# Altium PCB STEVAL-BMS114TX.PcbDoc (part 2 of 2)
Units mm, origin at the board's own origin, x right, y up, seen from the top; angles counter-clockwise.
Board outline 75.8 x 95.1 mm, 4 copper layers (Top Layer, Layer 1, Layer 2, Bottom Layer), stack 1.59 mm thick; 304 components, 148 nets, 694 pads, 400 vias.
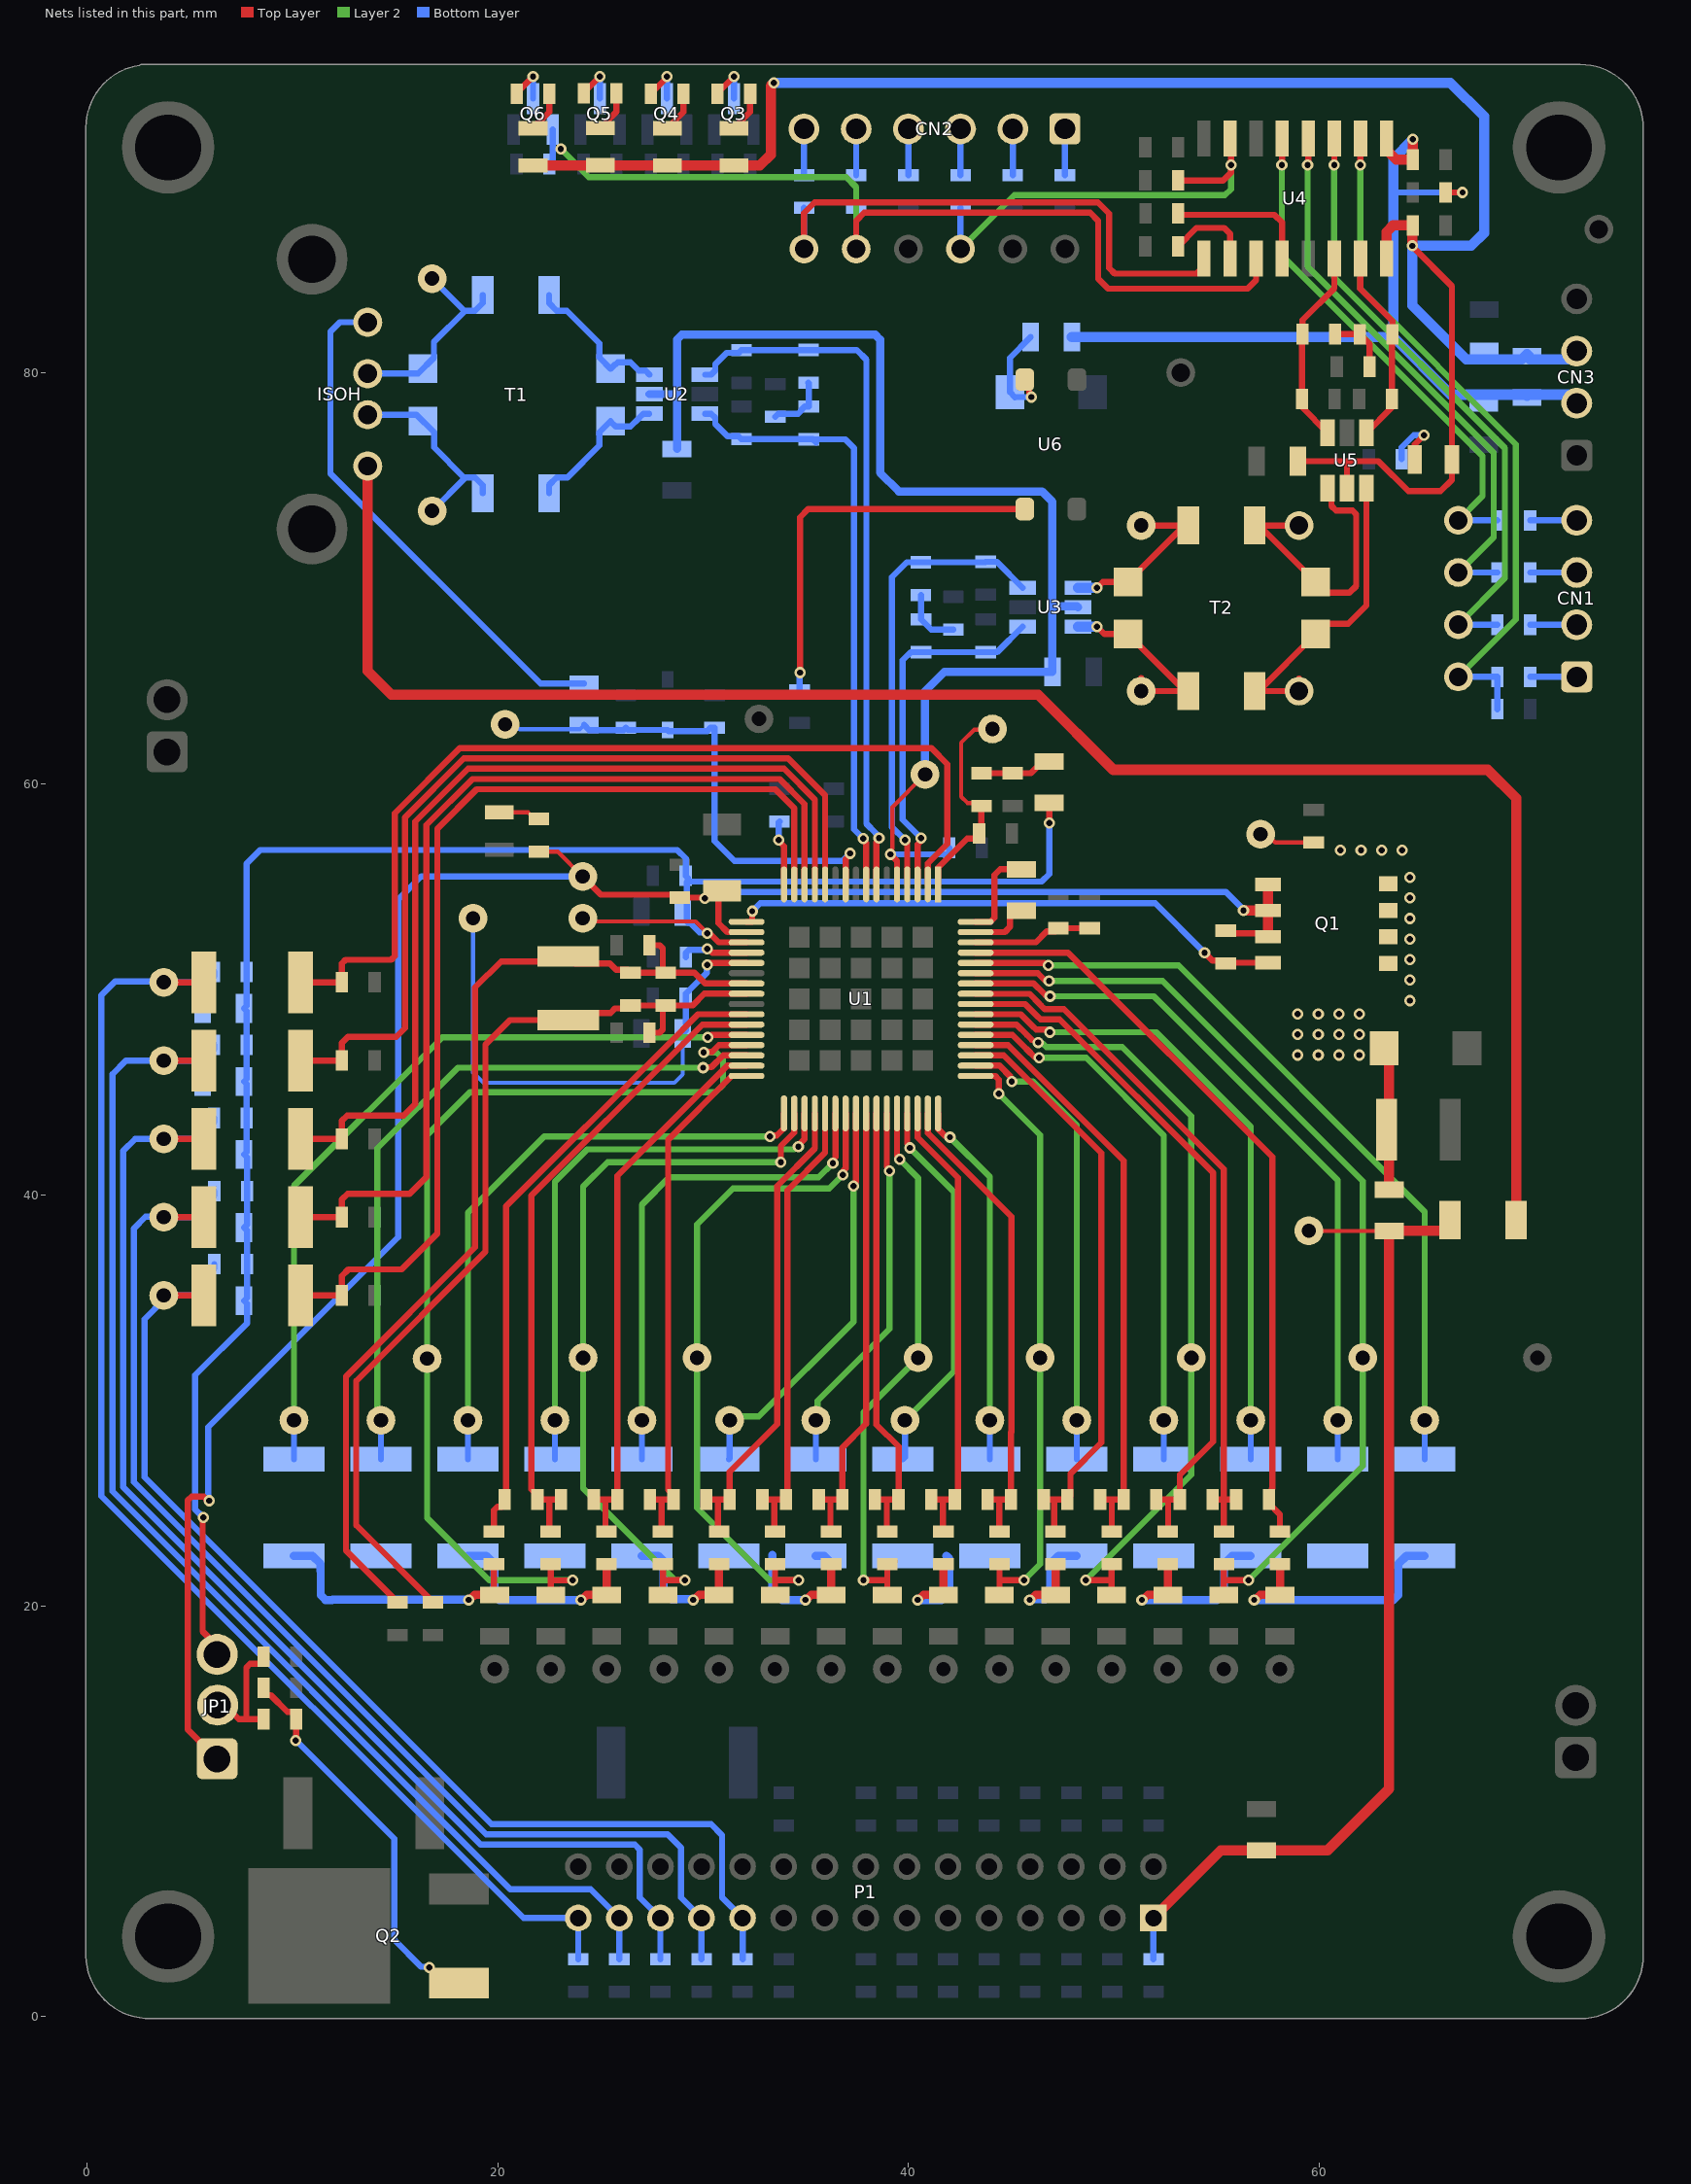
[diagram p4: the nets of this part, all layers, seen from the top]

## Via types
v1: diameter 0.55, hole 0.3, Top Layer to Bottom Layer, tented both sides, 364 vias
v2: diameter 0.55, hole 0.3, Top Layer to Bottom Layer, 36 vias

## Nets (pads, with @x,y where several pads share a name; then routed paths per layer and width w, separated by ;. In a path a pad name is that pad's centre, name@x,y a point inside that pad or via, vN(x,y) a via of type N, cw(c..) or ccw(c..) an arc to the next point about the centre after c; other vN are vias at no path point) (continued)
ISOFreq: R66.2 R80.2 TP10.1 U4.7 | length 22
  Top Layer w0.3: R66.2@53.121,89.372 55.309,89.372 55.695,89.758 v1(55.695,90.129) 55.695,91.367 U4.7@55.652,91.41
  Layer 2 w0.3: TP10.1@42.535,86.036 45.147,88.648 55.397,88.648 55.695,88.946 v1(55.695,90.129)
  Bottom Layer w0.3: TP10.1@42.535,86.036 R80.2@42.535,88.038
ISOLm: C81.2 ISOLm.1 T2.3 U3.4 | length 9
  Top Layer w0.3: v1(49.181,69.552) 49.462,69.833 T2.3@50.677,69.833 C81.2@53.422,72.578 ; ISOLm.1@51.322,72.295 ISOLm.1@51.322,72.578 C81.2@53.422,72.578 ; C81.2@53.618,72.578 C81.2@53.422,72.578
  Bottom Layer w0.5: U3.4@48.255,69.549 49.178,69.549 v1(49.181,69.552)
ISOLp: C27.2 ISOLp.1 T2.4 U3.6 | length 9.3
  Top Layer w0.3: v1(49.181,67.649) 49.537,67.293 T2.4@50.677,67.293 53.455,64.515 ISOLp.1@51.322,64.515 ISOLp.1@51.322,65.16
  Bottom Layer w0.5: U3.6@48.255,67.649 v1(49.181,67.649)
NCS: R73.2 TP7.1 U4.5 | length 25
  Top Layer w0.3: v1(58.171,90.129) 58.192,90.15 U4.5@58.192,91.41
  Layer 2 w0.3: v1(58.171,90.129) 58.171,85.728 67.944,75.955 67.944,74.008 TP7.1@66.764,72.828
  Bottom Layer w0.3: TP7.1@66.764,72.828 R73.2@68.665,72.828
NetB2_1_1: B2_1.1 FB15.2 R56.1 U1.29 | length 50.1
  Top Layer w0.3: R56.1@22.569,22.02 22.585,22.005 22.585,21.267 ; FB15.2@23.064,20.779 22.814,20.529 FB15.2@22.585,20.529 22.585,21.267 ; v1(23.652,21.246) 23.64,21.234 22.617,21.234 22.585,21.267 ; v1(30.03,46.937) 30.052,46.959 30.443,46.959 30.77,47.286 U1.29@32.116,47.286
  Layer 2 w0.3: v1(23.652,21.246) 19.592,21.246 16.568,24.27 16.568,32.07 16.568,42.909 18.647,44.988 30.608,44.988 30.97,45.35 30.97,46.624 30.658,46.937 v1(30.03,46.937)
NetB4_3_1: B4_3.1 FB13.2 R44.1 U1.34 | length 37
  Top Layer w0.3: FB13.2@28.046,20.529 28.046,21.246 ; R44.1@28.246,22.02 R44.1@28.046,22.02 28.046,21.246 ; v1(29.111,21.246) 28.046,21.246 ; v1(33.784,41.586) 33.784,42.367 33.896,42.479 33.896,42.484 34.441,43.029 U1.34@34.441,43.961
  Layer 2 w0.3: v1(29.111,21.246) 28.634,21.246 24.162,25.717 B4_3.1@24.162,32.07 24.162,40.399 25.349,41.586 v1(33.784,41.586)
NetB6_5_1: B6_5.1 FB11.2 R33.1 U1.39 | length 34.2
  Top Layer w0.3: FB11.2@33.507,20.529 33.507,21.275 ; R33.1@33.507,22.02 33.507,21.275 ; R33.1@33.657,22.17 R33.1@33.857,22.17 ; v1(34.653,21.246) 33.535,21.246 33.507,21.275 ; v1(36.802,40.974) 36.85,41.022 36.85,41.195 36.941,41.286 U1.39@36.941,43.961
  Layer 2 w0.3: B6_5.1@29.706,31.883 B6_5.1@29.706,31.824 ; v1(34.653,21.246) 33.235,21.246 29.706,24.775 B6_5.1@29.706,31.824 ; v1(36.802,40.974) 36.802,40.972 36.137,40.307 31.451,40.307 29.706,38.562 B6_5.1@29.706,31.824
NetB8_7_1: B8_7.1 FB9.2 R26.1 U1.44 | length 26.9
  Top Layer w0.3: v1(37.808,21.246) 38.939,21.246 38.968,21.275 ; FB9.2@38.968,20.529 38.968,21.275 ; R26.1@38.968,22.02 38.968,21.275 ; R26.1@39.168,22.02 R26.1@39.318,22.17 ; v1@39.441,41.919 U1.44@39.441,43.961
  Layer 2 w0.3: v1(37.808,21.246) 37.808,29.404 B8_7.1@40.52,32.116 ; v1(39.566,41.726) 40.474,40.818 B8_7.1@40.474,32.07
NetB10_9_1: B10_9.1 FB7.2 R21.1 U1.49 | length 29.4
  Top Layer w0.3: U1.49@43.266,45.786 44.225,45.786 44.401,45.61 44.401,44.931 v1(44.391,44.921) ; FB7.2@44.429,20.529 44.429,21.275 ; R21.1@44.429,22.02 44.429,21.275 ; v1(45.632,21.246) 44.458,21.246 44.429,21.275
  Layer 2 w0.3: v1(44.391,44.921) 46.408,42.904 B10_9.1@46.408,32.07 46.408,22.022 v1(45.632,21.246)
NetB12_11_1: B12_11.1 FB5.2 R14.1 U1.54 | length 39.3
  Top Layer w0.3: U1.54@43.266,48.286 43.982,48.286 45.261,48.286 45.76,47.787 45.836,47.711 46.008,47.538 ; v1(48.632,21.246) 49.767,21.246 ; FB5.2@49.89,20.529 49.89,21.123 49.89,21.246 R14.1@49.89,22.02
  Layer 2 w0.3: v1(46.31,47.413) 46.358,47.366 46.535,47.366 46.706,47.194 50.406,47.194 53.769,43.831 B12_11.1@53.769,32.07 53.769,26.383 v1(48.632,21.246)
NetB14_13_1: B14_13.1 FB3.2 R8.1 U1.59 | length 47.5
  Top Layer w0.3: U1.59@43.266,50.786 46.296,50.786 46.622,50.46 46.799,50.46 v1(46.847,50.412) ; FB3.2@55.351,20.529 55.351,21.123 R8.1@55.351,22.02 ; 55.351,21.246 v1(56.56,21.246)
  Layer 2 w0.3: v1(46.847,50.412) 52.36,50.412 62.113,40.659 62.113,32.413 B14_13.1@62.544,31.982 ; v1(56.56,21.246) 62.113,26.799 B14_13.1@62.113,31.824
NetC3_2: C3.2 C4.2 C5.2 C6.2 D1.2 FB1.2 Q1.5 Q1.6 Q1.7 Q1.8 TP1.1 U1.62 | length 15.6
  Top Layer w0.2: TP1.1@57.137,57.55 57.449,57.55 57.854,57.145 C6.2@59.722,57.145
  Top Layer w0.3: U1.62@43.266,52.286 46.186,52.286 46.728,52.828 47.146,52.828 C4.2@47.296,52.978 C5.2@48.817,52.978
  Top Layer w0.5: D1.2@63.16,47.132 63.399,46.893 FB1.2@63.399,40.258
  other v1: 58.949,46.801 59.949,46.801 60.949,46.801 61.949,46.801 58.949,47.801 59.949,47.801 60.949,47.801 61.949,47.801 58.949,48.801 59.949,48.801 60.949,48.801 61.949,48.801 64.4,49.451 64.4,50.451 64.4,51.451 64.4,52.451 64.4,53.451 64.4,54.451 64.4,55.451 61.031,56.772 62.031,56.772 63.031,56.772 64.031,56.772
NetC9_1: C9.1 C17.2 R8.2 U1.57 | length 34.6
  Top Layer w0.3: U1.57@43.266,49.786 43.991,49.786 45.882,49.786 46.381,49.287 46.457,49.211 46.63,49.038 47.567,49.038 55.351,41.255 55.351,25.173 ; C17.2@54.803,25.373 C17.2@54.803,25.173 55.351,25.173 ; R8.2@55.351,23.614 55.351,25.173 ; C9.1@55.949,25.173 55.351,25.173
NetC9_2: C9.2 R4.2 U1.61 | length 37.1
  Top Layer w0.3: U1.61@43.266,51.786 47.769,51.786 57.708,41.847 57.708,25.711 57.692,25.695 57.692,25.135 57.542,24.985 58.081,24.446 R4.2@58.081,23.614
NetC12_2: C12.2 C13.2 U1.21 VANA.1 | length 25.9
  Top Layer w0.3: v1(30.207,51.195) 30.275,51.195 30.366,51.286 U1.21@32.116,51.286
  Bottom Layer w0.2: VANA.1@18.805,53.461 18.805,45.951 19.306,45.45 28.6,45.45 29.012,45.862 C13.2@29.012,47.863
  Bottom Layer w0.3: C13.2@29.012,47.863 29.155,48.006 C12.2@29.155,49.588 29.155,49.788 29.305,49.938 29.314,49.938 30.176,50.8 30.176,51.164 v1(30.207,51.195)
NetC16_2: C16.2 R36.1 U4.15 U5.1 | length 9.6
  Top Layer w0.3: U4.15@62.002,85.56 62.002,84.086 63.557,82.531 R36.1@63.557,81.88 63.528,81.851 C16.2@63.528,78.738 63.528,78.333 U5.1@62.293,77.098
NetC17_1: C17.1 C20.2 R11.2 U1.56 | length 34.2
  Top Layer w0.3: U1.56@43.266,49.286 43.988,49.286 45.675,49.286 46.174,48.787 46.25,48.711 46.423,48.538 47.36,48.538 54.819,41.079 54.819,27.987 53.21,26.377 C17.1@53.21,25.173 52.637,25.173 ; C20.2@52.064,25.173 52.637,25.173 ; R11.2@52.62,23.614 52.637,23.631 52.637,25.173
NetC18_1: C18.1 U1.64 | length 4.5
  Top Layer w0.3: U1.64@43.266,53.286 43.991,53.286 44.19,53.485 44.19,55.567 44.468,55.845 C18.1@45.498,55.845
NetC18_2: C18.2 U1.63 | length 3
  Top Layer w0.3: U1.63@43.266,52.786 44.689,52.786 44.948,53.045 44.948,53.582 45.198,53.832 C18.2@45.498,53.832
NetC20_1: C20.1 C23.2 R14.2 U1.52 | length 28.7
  Top Layer w0.3: U1.52@43.266,47.286 44.847,47.286 50.471,41.662 C20.1@50.471,25.173 49.898,25.173 ; C23.2@49.325,25.173 49.898,25.173 ; R14.2@49.89,23.614 49.898,23.622 49.898,25.173
NetC22_2: C22.2 R15.2 U1.7 U2.1 | length 34.6
  Top Layer w0.3: U1.7@38.441,55.111 38.441,57.163 38.566,57.288 v1(38.566,57.356)
  Bottom Layer w0.3: U2.1@30.096,79.919 30.396,79.919 30.596,80.119 30.596,80.419 31.158,80.981 31.738,80.981 C22.2@31.866,81.109 35.122,81.109 R15.2@35.131,81.118 37.48,81.118 37.951,80.648 37.951,58.063 38.416,57.598 38.416,57.574 38.566,57.423 v1(38.566,57.356)
NetC23_1: C23.1 C30.2 R17.2 U1.51 | length 28.2
  Top Layer w0.3: U1.51@43.266,46.786 44.639,46.786 49.388,42.037 49.388,27.938 47.882,26.432 47.882,25.323 C23.1@47.732,25.173 ; C30.2@46.587,25.173 47.084,25.173 ; R17.2@47.159,23.614 47.084,23.688 47.084,25.173 ; C23.1@47.582,25.173 47.084,25.173
NetC24_1: C24.1 R15.1 R18.2 | length 3
  Bottom Layer w0.3: C24.1@33.517,77.865 33.667,78.015 34.621,78.015 34.797,78.191 34.797,78.213 34.947,78.363 R18.2@35.147,78.363 35.147,79.509 R15.1@35.131,79.525
NetC26_1: C26.1 R18.1 U1.8 U2.3 | length 30
  Top Layer w0.3: v1(37.791,57.339) 37.791,57.271 37.941,57.121 U1.8@37.941,55.111
  Bottom Layer w0.3: U2.3@30.096,78.019 30.396,78.019 30.596,77.819 30.596,77.519 31.185,76.93 31.716,76.93 C26.1@31.866,76.78 35.338,76.78 R18.1@35.347,76.77 ; R18.1@35.147,76.77 R18.1@35.347,76.77 ; R18.1@35.497,76.62 R18.1@35.347,76.77 ; v1(37.791,57.339) 37.344,57.786 37.344,76.347 36.921,76.77 35.497,76.77 R18.1@35.347,76.77
NetC27_1: C27.1 T2.1 TP2.1 U5.6 | length 15.3
  Top Layer w0.3: TP2.1@59.007,65.13 TP2.1@59.007,64.515 57.043,64.515 T2.1@59.821,67.293 60.329,67.801 61.404,67.801 62.293,68.69 U5.6@62.293,74.398
NetC28_1: C28.1 T1.1 U2.6 | length 7.3
  Bottom Layer w0.3: C28.1@22.504,83.798 22.504,83.397 22.878,83.023 23.376,83.023 24.953,81.447 24.953,80.75 T1.1@25.501,80.202 T1.1@25.714,80.415 ; T1.1@25.78,80.447 25.855,80.522 26.474,80.522 26.877,80.119 27.196,80.119 U2.6@27.396,79.919
NetC28_2: C28.2 ISOH.3 ISOHp.1 T1.4 | length 10.1
  Bottom Layer w0.3: ISOH.3@13.675,79.969 16.124,79.969 16.902,80.747 16.902,81.506 18.418,83.021 ; ISOHp.1@16.811,84.593 18.383,83.021 18.418,83.021 ; C28.2@19.278,83.798 19.278,83.397 18.904,83.023 18.73,83.023 18.728,83.021 18.418,83.021
NetC30_1: C30.1 C32.2 R21.2 U1.47 | length 23.2
  Top Layer w0.3: U1.47@40.941,43.961 40.941,43.001 45.007,38.935 45.007,28.462 44.993,28.448 C30.1@44.993,25.173 44.42,25.173 ; C32.2@43.848,25.173 44.42,25.173 ; R21.2@44.429,23.614 44.42,23.622 44.42,25.173
NetC32_1: C32.1 C35.2 R23.2 U1.46 | length 22.4
  Top Layer w0.3: U1.46@40.441,43.961 40.441,43.236 40.441,42.794 42.404,40.831 42.404,25.323 C32.1@42.254,25.173 41.682,25.173 ; C35.2@41.109,25.173 41.682,25.173 ; R23.2@41.698,23.614 41.682,23.63 41.682,25.173
NetC34_2: C34.2 R25.2 U1.3 U3.1 | length 17.9
  Top Layer w0.3: U1.3@40.441,55.111 40.441,57.056 40.559,57.174 40.559,57.323 v1(40.607,57.371)
  Bottom Layer w0.3: v1(40.607,57.371) 39.72,58.258 39.72,66.021 40.107,66.408 R25.2@40.612,66.408 C34.2@43.754,66.408 44.314,66.408 U3.1@45.555,67.649
NetC35_1: C35.1 C41.2 R26.2 U1.42 | length 21.9
  Top Layer w0.3: C41.2@38.37,25.173 38.943,25.173 ; U1.42@38.441,43.961 38.441,43.236 38.441,28.822 39.515,27.747 C35.1@39.515,25.173 38.943,25.173 ; R26.2@38.968,23.614 38.943,23.639 38.943,25.173
NetC36_1: C36.1 R25.1 R27.2 | length 3
  Bottom Layer w0.3: R27.2@40.604,69.196 40.604,68.01 R25.1@40.612,68.002 41.103,67.511 C36.1@42.183,67.511
NetC38_1: C38.1 T1.2 U2.4 | length 7.3
  Bottom Layer w0.3: C38.1@22.504,74.146 22.504,74.545 22.878,74.919 23.405,74.919 24.955,76.469 24.955,77.116 T1.2@25.501,77.662 ; T1.2@25.501,77.637 25.747,77.391 26.474,77.391 26.896,77.813 26.896,77.819 27.096,78.019 U2.4@27.374,78.019
NetC38_2: C38.2 ISOH.2 ISOHm.1 T1.3 | length 10.2
  Bottom Layer w0.3: ISOH.2@13.675,77.969 16.05,77.969 16.905,77.114 16.905,76.373 18.362,74.915 18.437,74.915 ; ISOHm.1@16.811,73.289 18.437,74.915 ; C38.2@19.278,74.146 19.278,74.541 18.904,74.915 18.437,74.915
NetC39_1: C39.1 R27.1 U1.4 U3.3 | length 22.5
  Top Layer w0.3: v1(39.824,57.27) 39.85,57.295 39.941,57.204 U1.4@39.941,55.111
  Bottom Layer w0.3: v1(39.824,57.27) 39.2,57.894 39.2,70.067 39.923,70.789 R27.1@40.604,70.789 43.736,70.789 C39.1@43.754,70.808 44.296,70.808 U3.3@45.555,69.549
NetC41_1: C41.1 C43.2 R29.2 U1.41 | length 22
  Top Layer w0.3: C43.2@35.631,25.173 36.204,25.173 ; R29.2@36.237,23.614 36.204,23.647 36.204,25.173 ; U1.41@37.941,43.961 37.941,28.853 36.777,27.689 C41.1@36.777,25.173 36.204,25.173
NetC43_1: C43.1 C46.2 R33.2 U1.37 | length 22.3
  Top Layer w0.3: C46.2@32.892,25.173 33.465,25.173 ; R33.2@33.507,23.614 33.465,23.655 33.465,25.173 ; U1.37@35.941,43.961 35.941,43.236 35.941,42.054 34.106,40.219 34.106,25.242 C43.1@34.038,25.173 33.465,25.173
NetC44_2: C44.2 D3.2 GPIO1.1 R30.1 R32.2 U1.10 | length 24.9
  Top Layer w0.3: U1.10@36.941,55.111 36.941,56.338 37.153,56.55 v1(37.153,56.618)
  Bottom Layer w0.2: GPIO1.1@20.364,62.901 20.594,62.672 21.066,62.672 21.081,62.657 23.999,62.657 R30.1@24.21,62.868
  Bottom Layer w0.3: R30.1@24.21,62.868 24.456,62.622 26.139,62.622 R32.2@26.242,62.725 26.343,62.624 D3.2@28.27,62.624 28.321,62.572 30.207,62.572 30.36,62.725 C44.2@30.56,62.725 30.56,57.227 31.533,56.254 36.789,56.254 v1(37.153,56.618)
NetC46_1: C46.1 C49.2 R40.2 U1.36 | length 23.2
  Top Layer w0.3: C49.2@30.153,25.173 30.726,25.173 ; R40.2@30.776,23.614 30.726,23.664 30.726,25.173 ; U1.36@35.441,43.961 35.441,42.261 33.606,40.426 33.606,28.832 31.299,26.525 C46.1@31.299,25.173 30.726,25.173
NetC49_1: C49.1 C51.2 R44.2 U1.32 | length 25.5
  Top Layer w0.3: C51.2@27.416,25.173 27.988,25.173 ; R44.2@28.046,23.614 27.988,23.671 27.988,25.173 ; U1.32@32.116,45.786 31.391,45.786 31.391,45.771 28.297,42.677 28.297,25.636 28.56,25.373 C49.1@28.56,25.173 27.988,25.173
NetC51_1: C51.1 C58.2 R51.2 U1.31 | length 27
  Top Layer w0.3: C58.2@24.678,25.173 25.25,25.173 ; R51.2@25.3,23.614 25.25,23.664 25.25,25.173 ; U1.31@32.116,46.286 31.184,46.286 28.06,43.162 25.822,40.924 C51.1@25.822,25.173 25.25,25.173
NetC58_1: C58.1 C60.2 R56.2 U1.27 | length 31.4
  Top Layer w0.3: C60.2@21.94,25.173 22.512,25.173 ; C60.2@21.94,25.373 21.644,25.669 21.644,39.964 29.037,47.357 29.966,48.286 U1.27@32.116,48.286 ; R56.2@22.569,23.614 22.512,23.671 22.512,25.173 ; C58.1@23.084,25.173 22.512,25.173
NetC60_1: C60.1 R60.2 U1.26 | length 31.8
  Top Layer w0.3: R60.2@19.82,23.614 19.82,24.647 19.996,24.823 20.196,24.823 20.346,24.973 C60.1@20.346,25.173 20.417,25.244 20.417,39.444 28.238,47.265 29.759,48.786 31.391,48.786 U1.26@32.116,48.786
NetC61_2: C61.2 R53.1 U1.2 | length 47.4
  Top Layer w0.3: R53.1@10.403,50.343 C61.2@12.421,50.343 12.421,51.264 12.597,51.44 14.817,51.44 14.992,51.616 14.992,58.577 18.153,61.738 41.119,61.738 41.892,60.966 41.892,57.082 40.941,56.131 U1.2@40.941,55.111
NetC62_2: C62.2 R54.1 U1.12 | length 43.2
  Top Layer w0.3: R54.1@10.403,46.533 C62.2@12.421,46.533 12.421,47.393 12.711,47.683 15.063,47.683 15.492,48.112 15.492,58.37 18.36,61.238 34.143,61.238 35.941,59.44 U1.12@35.941,55.111
NetC63_2: C63.2 R55.1 U1.13 | length 45.8
  Top Layer w0.3: R55.1@10.403,42.723 C63.2@12.421,42.723 12.421,43.611 12.672,43.862 15.429,43.862 15.992,44.426 15.992,58.163 18.567,60.738 33.936,60.738 35.441,59.233 U1.13@35.441,55.111
NetC64_2: C64.2 R57.1 U1.14 | length 48.3
  Top Layer w0.3: R57.1@10.403,38.913 C64.2@12.421,38.913 12.421,39.777 12.698,40.054 15.719,40.054 16.53,40.865 16.53,57.994 18.774,60.238 33.729,60.238 34.941,59.026 U1.14@34.941,55.111
NetC65_2: C65.2 R58.1 U1.15 | length 50.4
  Top Layer w0.3: R58.1@10.403,35.103 C65.2@12.421,35.103 12.421,36.059 12.736,36.374 15.329,36.374 17.062,38.107 17.062,57.819 18.981,59.738 33.522,59.738 34.441,58.819 U1.15@34.441,55.111
NetC72_1: C72.1 C73.1 C74.1 R7.2 R10.1 U1.24 | length 47
  Top Layer w0.3: R7.2@16.856,20.172 13.118,23.91 13.118,30.948 19.404,37.234 19.404,47.31 20.598,48.504 C72.1@23.431,48.504 23.781,48.854 25.501,48.854 25.717,49.07 26.318,49.07 C73.1@26.465,49.217 C74.1@28.19,49.217 ; R10.1@27.387,47.888 27.887,47.888 28.037,48.038 28.037,48.412 28.038,48.413 28.038,49.067 28.188,49.217 C74.1@28.19,49.217 ; U1.24@32.116,49.786 30.062,49.786 29.493,49.217 C74.1@28.19,49.217
NetC72_2: C72.2 C73.2 C74.2 R3.2 R13.1 U1.23 | length 49.7
  Top Layer w0.3: R3.2@15.131,20.172 12.618,22.685 12.618,31.155 18.904,37.441 18.904,50.093 20.174,51.363 23.191,51.363 C72.2@23.431,51.603 23.773,51.26 25.464,51.26 25.771,50.953 26.322,50.953 C73.2@26.465,50.81 C74.2@27.93,50.81 ; R13.1@27.387,52.146 27.887,52.146 28.037,51.996 28.037,51.622 28.038,51.621 28.038,50.877 28.105,50.81 C74.2@28.19,50.81 29.576,50.81 30.1,50.286 U1.23@32.116,50.286
NetC79_2: C79.2 R36.2 R42.1 | length 3
  Top Layer w0.3: R42.1@60.77,81.889 61.955,81.889 R36.2@61.964,81.88 62.436,81.408 C79.2@62.436,80.309
NetC81_1: C81.1 T2.2 TP3.1 U5.4 | length 14.5
  Top Layer w0.3: C81.1@56.844,72.578 C81.1@57.076,72.578 ; TP3.1@59.007,72.31 TP3.1@59.007,72.578 C81.1@57.076,72.578 ; U5.4@60.393,74.398 60.585,74.205 60.585,73.529 60.812,73.302 61.609,73.302 61.793,73.118 61.793,69.629 61.464,69.3 60.354,69.3 T2.2@59.821,69.833 C81.1@57.076,72.578
NetC82_2: C82.2 R42.2 U4.14 U5.3 | length 9.6
  Top Layer w0.3: U5.3@60.393,77.098 59.154,78.336 C82.2@59.154,78.738 59.154,81.867 R42.2@59.176,81.889 59.176,82.57 60.732,84.126 U4.14@60.732,85.56
NetCGS_2: CGS.2 Q2.1 RG.1 | length 17.5
  Top Layer w0.3: CGS.2@8.603,15.999 8.603,15.799 8.753,15.649 8.953,15.649 9.774,14.828 10.046,14.828 10.196,14.678 10.196,13.467 v1(10.171,13.442)
  Bottom Layer w0.3: v1(10.171,13.442) 10.189,13.442 14.966,8.665 14.966,3.741 16.279,2.428 16.631,2.428 v1(16.667,2.392)
NetCN1_1: CN1.1 R69.1 | length 2.3
  Bottom Layer w0.3: R69.1@70.259,65.208 CN1.1@72.528,65.208
NetCN1_2: CN1.2 R70.1 | length 2.3
  Bottom Layer w0.3: R70.1@70.259,67.748 CN1.2@72.528,67.748
NetCN1_3: CN1.3 R72.1 | length 2.3
  Bottom Layer w0.3: R72.1@70.259,70.288 CN1.3@72.528,70.288
NetCN1_4: CN1.4 R73.1 | length 2.3
  Bottom Layer w0.3: R73.1@70.259,72.828 CN1.4@72.528,72.828
NetCN2_1: CN2.1 R75.1 | length 2.3
  Bottom Layer w0.3: R75.1@47.615,89.631 CN2.1@47.615,91.881
NetCN2_2: CN2.2 R76.1 | length 2.3
  Bottom Layer w0.3: R76.1@45.075,89.631 CN2.2@45.075,91.881
NetCN2_3: CN2.3 R80.1 | length 2.3
  Bottom Layer w0.3: R80.1@42.535,89.631 CN2.3@42.535,91.881
NetCN2_4: CN2.4 R82.1 | length 2.3
  Bottom Layer w0.3: R82.1@39.995,89.631 CN2.4@39.995,91.881
NetCN2_5: CN2.5 R83.1 | length 2.3
  Bottom Layer w0.3: R83.1@37.455,89.631 CN2.5@37.455,91.881
NetCN2_6: CN2.6 R84.1 | length 2.3
  Bottom Layer w0.3: R84.1@34.915,89.631 CN2.6@34.915,91.881
NetD2_1: D2.1 R5.1 | length 2
  Top Layer w0.2: D2.1@20.088,58.612 21.486,58.612 21.603,58.495 21.803,58.294 R5.1@22.003,58.294
NetD4_2: D4.2 R67.2 U6.4 | length 5.2
  Top Layer w0.3: U6.4@45.66,79.677 45.877,79.46 45.877,78.938 v1(45.987,78.827)
  Bottom Layer w0.3: R67.2@45.943,81.746 44.935,80.737 D4.2@44.935,79.068 45.184,78.819 45.192,78.827 v1(45.987,78.827)
NetD5_2: D5.2 R74.2 | length 2
  Top Layer w0.3: D5.2@31.504,91.908 32.294,92.698 R74.2@32.294,93.595
NetD6_2: D6.2 R77.2 | length 2
  Top Layer w0.3: D6.2@28.257,91.908 29.05,92.701 R77.2@29.05,93.595
NetD7_2: D7.2 R78.2 | length 2
  Top Layer w0.3: D7.2@24.994,91.918 25.787,92.711 R78.2@25.787,93.605
NetD8_2: D8.2 R79.2 | length 2
  Top Layer w0.3: D8.2@21.726,91.908 22.519,92.701 R79.2@22.519,93.595
NetD9_2: D9.2 R89.2 | length 3.3
  Top Layer w0.3: D9.2@64.64,75.787 64.64,76.524 v1(65.086,76.97)
  Bottom Layer w0.3: R89.2@64.001,75.807 64.001,76.383 64.588,76.97 v1(65.086,76.97)
NetFB2_2: FB2.2 R4.1 R6.1 | length 12.9
  Top Layer w0.4: v1(56.824,20.284) 56.865,20.284 57.109,20.529 FB2.2@58.081,20.529 R4.1@58.081,22.02
  Bottom Layer w0.4: v1(56.824,20.284) 63.604,20.284 63.838,20.518 63.838,22.029 64.238,22.429 R6.1@65.126,22.429
NetFB4_2: FB4.2 R9.1 R11.1 R12.1 | length 9.9
  Top Layer w0.4: v1(51.362,20.284) 51.403,20.284 51.647,20.529 FB4.2@52.62,20.529 R11.1@52.62,22.02
  Bottom Layer w0.4: v1(51.362,20.284) 55.01,20.284 55.358,20.632 55.358,22.029 55.758,22.429 R12.1@56.658,22.429
NetFB6_2: FB6.2 R16.1 R17.1 R19.1 | length 6.9
  Top Layer w0.4: v1(45.9,20.284) 45.941,20.284 46.185,20.529 FB6.2@47.159,20.529 R17.1@47.159,22.02
  Bottom Layer w0.4: v1(45.9,20.284) 45.929,20.313 46.665,20.313 46.899,20.547 46.899,22.029 47.299,22.429 R19.1@48.191,22.429
NetFB8_2: FB8.2 R22.1 R23.1 R24.1 | length 6.4
  Top Layer w0.4: v1(40.438,20.284) 40.479,20.284 40.723,20.529 FB8.2@41.698,20.529 R23.1@41.698,22.02
  Bottom Layer w0.4: v1(40.438,20.284) 41.597,20.284 41.983,20.67 41.983,22.286 41.84,22.429
NetFB10_2: FB10.2 R28.1 R29.1 R31.1 | length 7.3
  Top Layer w0.4: v1(34.976,20.284) 35.017,20.284 35.261,20.529 FB10.2@36.237,20.529 R29.1@36.237,22.02
  Bottom Layer w0.4: 33.368,22.473 33.368,20.773 33.857,20.284 v1(34.976,20.284) ; R28.1@35.489,22.429 35.896,22.429 R28.1@36.296,22.029
NetFB12_2: FB12.2 R38.1 R40.1 R41.1 | length 7.1
  Top Layer w0.4: v1(29.514,20.284) 29.555,20.284 29.799,20.529 FB12.2@30.776,20.529 R40.1@30.776,22.02
  Bottom Layer w0.4: R38.1@27.021,22.429 27.825,22.429 28.081,22.174 28.081,20.691 28.459,20.313 29.485,20.313 v1(29.514,20.284)
NetFB14_2: FB14.2 R50.1 R51.1 R52.1 | length 10.1
  Top Layer w0.4: v1(24.052,20.284) 24.093,20.284 24.337,20.529 FB14.2@25.315,20.529 25.315,22.005 R51.1@25.3,22.02
  Bottom Layer w0.4: R50.1@18.554,22.429 19.442,22.429 19.842,22.029 19.842,20.518 20.076,20.284 v1(24.052,20.284)
NetFB16_2: FB16.2 R59.1 R60.1 | length 13.2
  Top Layer w0.3: R60.1@19.82,22.02 19.82,20.563 FB16.2@19.854,20.529
  Top Layer w0.4: v1(18.59,20.284) 18.631,20.284 18.875,20.529 FB16.2@19.854,20.529
  Bottom Layer w0.4: R59.1@10.086,22.429 10.986,22.429 11.386,22.029 11.386,21.695 11.388,21.693 11.388,20.519 11.622,20.285 11.954,20.285 11.968,20.299 18.575,20.299 v1(18.59,20.284)
NetISOH_1: ISOH.1 R1.1 | length 89
  Top Layer w0.5: ISOH.1@13.675,75.469 13.675,65.504 14.836,64.343 46.307,64.343 49.965,60.685 68.194,60.685 69.582,59.297 R1.1@69.582,38.772
NetISOH_4: ISOH.4 R30.2 | length 25.5
  Bottom Layer w0.3: ISOH.4@13.675,82.469 12.316,82.469 11.861,82.013 11.861,75.106 22.086,64.881 R30.2@24.21,64.881
NetJP1_2: JP1.2 RG.2 RPD.2 | length 6.2
  Top Layer w0.3: JP1.2@6.373,15.165 6.712,15.165 7.399,14.478 7.77,14.478 ; RG.2@8.603,14.478 7.77,14.478 ; RPD.2@8.603,17.52 8.603,17.32 8.453,17.17 7.946,17.17 7.77,16.994 7.77,14.478
NetQ1_4: Q1.4 RMREG.1 U1.17 | length 27.3
  Top Layer w0.3: U1.17@32.116,53.286 32.395,53.286 v1(32.395,53.804) ; v1(54.415,51.786) 54.791,51.41 55.292,51.41 RMREG.1@55.442,51.26 55.477,51.296 Q1.4@57.493,51.296
  Bottom Layer w0.3: v1(32.395,53.804) 32.782,54.19 52.011,54.19 v1(54.415,51.786)
NetQ3_3: Q3.3 R74.1 | length 2.2
  Top Layer w0.3: R74.1@30.7,93.595 30.7,93.629 v1(31.504,94.433)
  Bottom Layer w0.3: Q3.3@31.501,93.356 31.501,94.43 v1(31.504,94.433)
NetQ4_3: Q4.3 R77.1 | length 2.2
  Top Layer w0.3: R77.1@27.457,93.595 28.237,94.376 v1(28.237,94.433)
  Bottom Layer w0.3: Q4.3@28.237,93.356 v1(28.237,94.433)
NetQ5_3: Q5.3 R78.1 | length 2.2
  Top Layer w0.3: R78.1@24.193,93.605 24.193,93.643 v1(24.984,94.433)
  Bottom Layer w0.3: Q5.3@24.984,93.356 v1(24.984,94.433)
NetQ6_3: Q6.3 R79.1 | length 2.2
  Top Layer w0.3: R79.1@20.926,93.595 20.926,93.633 v1(21.726,94.433)
  Bottom Layer w0.3: Q6.3@21.726,93.356 v1(21.726,94.433)
NetR6_2: R6.2 S14.1 U1.60 | length 38.9
  Top Layer w0.3: U1.60@43.266,51.286 46.613,51.286 46.738,51.161 v1(46.805,51.161)
  Layer 2 w0.3: v1(46.805,51.161) 53.14,51.161 65.126,39.175 S14.1@65.126,29.028
  Bottom Layer w0.3: R6.2@65.126,27.129 S14.1@65.126,29.028
NetR9_2: R9.2 S13.1 U1.58 | length 35.2
  Top Layer w0.3: U1.58@43.266,50.286 43.991,50.286 46.089,50.286 46.588,49.787 46.664,49.711 46.841,49.711 v1(46.889,49.663)
  Layer 2 w0.3: v1(46.889,49.663) 51.94,49.663 60.892,40.711 S13.1@60.892,29.028
  Bottom Layer w0.3: R9.2@60.892,27.129 S13.1@60.892,29.028
NetR12_2: R12.2 S12.1 U1.55 | length 31.6
  Top Layer w0.3: U1.55@43.266,48.786 43.985,48.786 45.468,48.786 45.967,48.287 46.043,48.211 46.216,48.038 v1@46.685,48.038
  Layer 2 w0.3: v1(46.878,47.913) 52.062,47.913 56.658,43.317 S12.1@56.658,29.028
  Bottom Layer w0.3: R12.2@56.658,27.129 S12.1@56.658,29.028
NetR16_2: R16.2 S11.1 U1.53 | length 27.2
  Top Layer w0.3: U1.53@43.266,47.786 43.979,47.786 45.054,47.786 45.552,47.287 45.628,47.211 45.801,47.038 46.127,46.712 46.304,46.712 v1(46.352,46.665)
  Layer 2 w0.3: v1(46.352,46.665) 48.646,46.665 52.424,42.887 S11.1@52.424,29.028
  Bottom Layer w0.3: R16.2@52.424,27.129 S11.1@52.424,29.028 S11.1@52.635,29.238
NetR19_2: R19.2 S10.1 U1.50 | length 22.5
  Top Layer w0.3: U1.50@43.266,46.286 43.991,46.286 44.432,46.286 44.978,45.74 44.978,45.563 v1(45.026,45.516)
  Layer 2 w0.3: v1(45.026,45.516) 46.063,45.516 48.191,43.388 S10.1@48.191,29.028
  Bottom Layer w0.3: R19.2@48.191,27.129 S10.1@48.191,29.028
NetR20_1: R20.1 U1.20 | length 3.3
  Top Layer w0.3: v1(30.207,51.964) 30.275,51.964 30.453,51.786 U1.20@32.116,51.786
  Bottom Layer w0.3: R20.1@29.163,51.567 29.163,51.767 29.313,51.917 30.16,51.917 v1(30.207,51.964)
NetR22_2: R22.2 S9.1 U1.48 | length 18
  Top Layer w0.3: U1.48@41.441,43.961 41.441,43.208 41.796,42.853 41.973,42.853 v1(42.02,42.805)
  Layer 2 w0.3: v1(42.02,42.805) 43.957,40.869 S9.1@43.957,29.028
  Bottom Layer w0.3: R22.2@43.957,27.129 S9.1@43.957,29.028
NetR24_2: R24.2 S8.1 U1.45 | length 18.8
  Top Layer w0.3: v1@39.941,42.478 U1.45@39.941,43.961
  Layer 2 w0.3: S8.1@39.823,29.028 42.219,31.424 42.219,40.132 v1(40.066,42.285)
  Bottom Layer w0.3: R24.2@39.723,27.129 39.823,27.229 S8.1@39.823,29.028 S8.1@40.021,29.226
NetR28_2: R28.2 S7.1 U1.43 | length 18.7
  Top Layer w0.3: U1.43@38.941,43.961 38.941,41.467 38.941,41.36 39.066,41.235 v1(39.066,41.167)
  Layer 2 w0.3: S7.1@35.489,29.028 35.566,29.105 35.566,29.977 39.066,33.477 v1(39.066,41.167)
  Bottom Layer w0.3: R28.2@35.489,27.129 S7.1@35.489,29.028 S7.1@35.7,29.238
NetR31_2: R31.2 S6.1 U1.40 | length 20.4
  Top Layer w0.3: v1(37.316,40.428) 37.316,40.495 37.441,40.62 U1.40@37.441,43.961
  Layer 2 w0.3: S6.1@31.299,29.028 31.488,29.217 32.718,29.217 37.316,33.815 v1(37.316,40.428)
  Bottom Layer w0.3: R31.2@31.255,27.129 31.299,27.173 S6.1@31.299,29.028 S6.1@31.509,29.238
NetR34_1: R34.1 R35.2 R37.2 | length 3.5
  Top Layer w0.3: R37.2@43.549,60.518 R35.2@45.07,60.518 45.96,60.518 46.544,61.103 R34.1@46.844,61.103
NetR38_2: R38.2 S5.1 U1.38 | length 24.6
  Top Layer w0.3: 36.441,41.847 U1.38@36.441,43.961
  Layer 2 w0.3: S5.1@27.021,29.028 27.021,39.517 28.35,40.846 35.617,40.846 v1(36.316,41.545)
  Bottom Layer w0.3: R38.2@27.021,27.129 S5.1@27.021,29.028
NetR41_2: R41.2 S4.1 U1.35 | length 27.8
  Top Layer w0.3: v1(34.637,42.341) 34.637,42.409 34.941,42.713 U1.35@34.941,43.961
  Layer 2 w0.3: S4.1@22.788,29.028 22.788,40.643 24.356,42.211 34.439,42.211 34.57,42.341 v1(34.637,42.341)
  Bottom Layer w0.3: R41.2@22.788,27.129 S4.1@22.788,29.028
NetR43_1: R43.1 U1.16 | length 3.2
  Top Layer w0.3: v1(33.679,57.264) 33.679,57.225 33.941,56.963 U1.16@33.941,55.111
  Bottom Layer w0.3: v1(33.679,57.264) 33.679,58.13 R43.1@33.721,58.172
NetR50_2: R50.2 S3.1 U1.33 | length 29.8
  Top Layer w0.3: v1(33.261,42.836) 33.309,42.884 33.589,42.884 33.941,43.236 U1.33@33.941,43.961
  Layer 2 w0.3: S3.1@18.554,29.028 18.554,39.124 22.266,42.836 v1(33.261,42.836)
  Bottom Layer w0.3: R50.2@18.554,27.129 S3.1@18.554,29.028
NetR52_2: R52.2 S2.1 U1.30 | length 35.1
  Top Layer w0.3: v1(30.003,46.187) 30.029,46.213 30.403,46.213 30.977,46.786 U1.30@32.116,46.786
  Layer 2 w0.3: S2.1@14.32,29.028 14.143,29.204 14.143,42.266 18.064,46.187 v1(30.003,46.187)
  Bottom Layer w0.3: R52.2@14.32,27.129 S2.1@14.32,29.028 S2.1@14.32,29.051
NetR59_2: R59.2 S1.1 U1.28 | length 38.4
  Top Layer w0.3: v1(30.225,47.661) 30.293,47.661 30.418,47.786 U1.28@32.116,47.786
  Layer 2 w0.3: S1.1@10.086,29.028 10.086,40.442 17.305,47.661 v1(30.225,47.661)
  Bottom Layer w0.3: R59.2@10.086,27.129 S1.1@10.086,29.028
NetR63_1: R63.1 U4.12 | length 7
  Top Layer w0.3: R63.1@53.128,87.763 53.128,87.695 57.813,87.695 58.181,87.327 58.181,85.571 U4.12@58.192,85.56
NetR64_2: R64.2 U4.10 | length 4.2
  Top Layer w0.3: R64.2@53.121,86.153 54.03,87.063 55.362,87.063 55.652,86.773 U4.10@55.652,85.56
NetR68_1: R68.1 U6.1 | length 19.5
  Top Layer w0.3: v1(34.714,65.416) 34.714,72.976 35.115,73.377 U6.1@45.66,73.377
  Bottom Layer w0.3: R68.1@34.697,64.561 34.697,65.399 v1(34.714,65.416)
NTC1+: C56.1 C70.2 GPIO6.1 P1.21 R49.1 R58.2 | length 57
  Top Layer w0.3: GPIO6.1@3.85,35.103 R58.2@5.703,35.103
  Bottom Layer w0.3: R49.1@5.644,34.849 R49.1@5.644,34.853 ; C56.1@6.206,36.628 6.206,36.428 6.056,36.278 5.856,36.278 5.644,36.066 R49.1@5.644,34.853 ; C70.2@31.924,2.803 P1.21@31.924,4.803 30.924,5.803 30.924,8.834 30.392,9.366 28.492,9.366 28.482,9.376 19.708,9.376 2.82,26.264 2.82,33.955 3.75,34.884 GPIO6.1@3.75,35.103 5.394,35.103 R49.1@5.644,34.853
NTC2+: C55.1 C69.2 GPIO5.1 P1.23 R48.1 R57.2 | length 59.9
  Top Layer w0.3: GPIO5.1@3.85,38.913 R57.2@5.703,38.913
  Bottom Layer w0.3: R48.1@5.644,38.405 R48.1@5.644,38.663 ; C55.1@6.206,40.18 6.206,39.98 6.056,39.83 5.856,39.83 5.644,39.618 R48.1@5.644,38.663 ; C69.2@29.924,2.803 P1.23@29.924,4.803 28.924,5.803 28.924,8.227 28.275,8.876 20.232,8.876 19.44,8.876 2.288,26.028 2.288,38.355 2.864,38.931 3.732,38.931 GPIO5.1@3.75,38.913 5.394,38.913 R48.1@5.644,38.663
NTC3+: C54.1 C68.2 GPIO4.1 P1.25 R47.1 R55.2 | length 62.7
  Top Layer w0.3: GPIO4.1@3.85,42.723 R55.2@5.703,42.723
  Bottom Layer w0.3: R47.1@5.644,41.961 5.644,42.878 ; C54.1@6.19,43.739 6.19,43.539 6.04,43.389 5.84,43.389 5.644,43.193 5.644,42.878 ; C68.2@27.924,2.803 P1.25@27.924,4.803 26.924,5.803 26.924,8.131 26.679,8.376 19.172,8.376 1.775,25.773 1.775,42.142 2.356,42.723 GPIO4.1@3.75,42.723 5.49,42.723 5.644,42.878
NTC4+: C53.1 C67.2 GPIO3.1 P1.27 R46.1 R54.2 | length 64.2
  Top Layer w0.3: GPIO3.1@3.85,46.533 R54.2@5.703,46.533
  Bottom Layer w0.3: R46.1@5.644,45.517 5.644,46.51 ; C53.1@6.19,47.295 6.19,47.095 6.04,46.945 5.84,46.945 5.644,46.749 5.644,46.51 ; C67.2@25.924,2.803 P1.27@25.924,4.803 24.52,6.207 20.612,6.207 1.245,25.574 1.245,45.876 1.902,46.533 GPIO3.1@3.75,46.533 5.621,46.533 5.644,46.51
NTC5+: C52.1 C66.2 GPIO9.1 P1.29 R45.1 R53.2 | length 67.3
  Top Layer w0.3: GPIO9.1@3.85,50.343 R53.2@5.703,50.343
  Bottom Layer w0.3: R45.1@5.644,49.073 5.644,50.305 ; C52.1@6.19,50.851 6.19,50.651 6.04,50.501 5.84,50.501 5.644,50.305 ; C66.2@23.924,2.803 P1.29@23.924,4.803 21.256,4.803 0.716,25.343 0.716,49.712 1.382,50.378 3.715,50.378 GPIO9.1@3.75,50.343 5.606,50.343 5.644,50.305
NTC_INTERNAL_INPUT: C47.2 GPIO8.1 R37.1 U1.1 | length 10.5
  Top Layer w0.2: R37.1@43.549,58.925 43.404,59.07 42.869,59.07 42.565,59.374 42.565,62.002 43.202,62.64 44.052,62.64 GPIO8.1@44.085,62.672
  Top Layer w0.3: U1.1@41.441,55.111 41.441,55.924 42.864,57.347 43.288,57.347 43.438,57.497 C47.2@43.438,57.596 43.549,57.706 R37.1@43.549,58.925
SCK: R70.2 TP5.1 U4.3 | length 29.9
  Top Layer w0.3: v1(60.725,90.116) 60.732,90.122 U4.3@60.732,91.41
  Layer 2 w0.3: v1(60.725,90.116) 60.721,90.112 60.721,84.652 69.028,76.345 69.028,70.012 TP5.1@66.764,67.748
  Bottom Layer w0.3: TP5.1@66.764,67.748 R70.2@68.665,67.748
SDI: R72.2 TP6.1 U4.4 | length 27.8
  Top Layer w0.3: v1(59.43,90.115) 59.462,90.146 U4.4@59.462,91.41
  Layer 2 w0.3: v1(59.43,90.115) 59.43,85.177 68.486,76.121 68.486,72.01 TP6.1@66.546,70.07
  Bottom Layer w0.3: TP6.1@66.764,70.288 R72.2@68.665,70.288
SDO: R69.2 R71.2 TP4.1 U4.2 | length 34
  Top Layer w0.3: v1(61.987,90.12) 62.002,90.135 U4.2@62.002,91.41
  Layer 2 w0.3: v1(61.987,90.12) 61.987,84.11 69.568,76.528 69.568,68.512 69.568,68.012 TP4.1@66.764,65.208
  Bottom Layer w0.3: TP4.1@66.764,65.208 R69.2@68.665,65.208 R71.2@68.665,63.637
TXAmp: R84.2 TP13.1 U4.9 | length 26.9
  Top Layer w0.3: TP13.1@34.915,86.036 34.915,87.787 35.427,88.3 49.213,88.3 49.759,87.754 49.759,85.109 50.035,84.833 54.022,84.833 54.382,85.193 U4.9@54.382,85.56
  Bottom Layer w0.3: TP13.1@34.915,86.036 R84.2@34.915,88.038
TXEN: Q6.1 R83.2 R87.2 TP12.1 U4.11 | length 47.3
  Top Layer w0.3: TP12.1@37.455,86.036 37.455,87.406 37.848,87.8 48.835,87.8 49.235,87.4 49.235,84.592 49.723,84.104 56.504,84.104 56.922,84.521 U4.11@56.922,85.56
  Layer 2 w0.3: v1(23.076,90.895) 24.434,89.537 36.966,89.537 37.455,89.048 TP12.1@37.455,86.036
  Bottom Layer w0.3: R87.2@22.518,90.168 22.676,90.326 Q6.1@22.676,91.856 ; TP12.1@37.455,86.036 R83.2@37.455,88.038
VBAT_BMS: C1.2 FB1.1 P1.1 R1.2 R2.2 VBATT.1 | length 50.5
  Top Layer w0.2: VBATT.1@59.492,38.245 FB1.1@63.399,38.245 ; VBATT.1@59.984,38.253 VBATT.1@59.992,38.245
  Top Layer w0.5: P1.1@51.924,4.803 55.214,8.093 R2.2@57.18,8.093 60.398,8.093 63.399,11.094 FB1.1@63.399,38.245 66.082,38.245 66.356,38.519 R1.2@66.356,38.772
  Bottom Layer w0.3: C1.2@51.924,2.803 P1.1@51.924,4.803
VCOM: C10.2 C25.1 C37.1 U1.5 U2.5 U3.5 VCOM.1 | length 61.7
  Top Layer w0.2: v1(39.123,56.568) 39.19,56.635 39.19,56.837 39.213,56.86 39.213,58.871 VCOM.1@40.808,60.466
  Top Layer w0.3: v1(39.123,56.568) 39.441,56.25 39.441,55.836 U1.5@39.441,55.111
  Bottom Layer w0.3: v1(39.123,56.568) 41.979,56.568 C10.2@41.979,56.889
  Bottom Layer w0.4: U2.5@27.396,78.969 28.727,78.969 ; C25.1@28.727,76.306 28.727,78.969 ; VCOM.1@40.808,60.466 40.808,64.514 41.755,65.461 C37.1@47.003,65.461 47.003,68.655 ; U3.5@48.255,68.599 48.199,68.655 47.003,68.655 ; 28.727,78.969 28.727,81.622 28.961,81.857 38.386,81.857 38.62,81.622 38.62,75.144 39.531,74.233 46.499,74.233 47.003,73.729 47.003,68.655
VDD: C78.2 C80.2 C84.2 CN3.3 D5.1 D6.1 D7.1 D8.1 D9.1 R88.2 U4.16 U5.5 | length 98.2
  Top Layer w0.3: C80.2@58.952,75.706 61.214,75.706 ; U5.5@61.343,74.398 61.343,75.577 61.214,75.706 ; v1(64.517,86.188) 64.517,86.16 66.453,84.224 D9.1@66.453,75.787 66.453,74.803 65.9,74.25 64.332,74.25 62.876,75.706 61.343,75.706 61.214,75.706
  Top Layer w0.5: D8.1@21.726,90.095 D6.1@28.257,90.095 D5.1@31.504,90.095 32.766,90.095 33.293,90.622 33.293,93.965 v1(33.452,94.124) ; U4.16@63.272,85.56 63.272,86.866 63.591,87.185 C78.2@64.555,87.185 64.517,87.147 v1(64.517,86.188)
  Bottom Layer w0.5: v1(33.452,94.124) 66.376,94.124 68.02,92.48 68.02,86.82 67.388,86.188 v1(64.517,86.188) 64.517,83.292 67.154,80.655 69.853,80.655 70.107,80.909 R88.2@70.25,80.766 ; R88.2@70.107,80.809 70.249,80.667 72.129,80.667 CN3.3@72.528,81.067
VIO: C77.2 C83.1 CN3.2 R62.1 R67.1 R88.1 U4.1 | length 43.2
  Top Layer w0.3: R62.1@66.148,88.785 66.967,88.785 v1(66.969,88.787)
  Top Layer w0.5: U4.1@63.272,91.41 63.272,90.86 63.747,90.385 C77.2@64.555,90.385 v1(64.555,91.369)
  Bottom Layer w0.3: 63.597,88.785 66.967,88.785 v1(66.969,88.787)
  Bottom Layer w0.5: R67.1@47.956,81.746 63.597,81.746 66.397,78.945 70.058,78.945 70.107,78.896 70.156,78.945 72.11,78.945 CN3.2@72.528,78.527 ; 63.627,81.746 63.597,81.776 63.597,88.785 63.597,90.411 v1(64.555,91.369)
VREG: C2.2 C7.2 JP1.1 Q1.1 Q1.2 Q1.3 R5.2 RMREG.2 U1.18 VREG.1 | length 102.5
  Top Layer w0.2: R5.2@22.003,56.701 22.934,56.701 VREG.1@24.144,55.491
  Top Layer w0.3: v1(5.96,25.115) 5.892,25.115 5.695,25.312 5.101,25.312 4.925,25.137 4.925,13.971 JP1.1@6.348,12.549 ; VREG.1@24.144,55.491 25.027,54.608 28.727,54.608 C7.2@28.871,54.464 30.589,54.464 C2.2@30.748,54.623 ; C2.2@30.927,54.802 C2.2@30.748,54.623 ; U1.18@32.116,52.786 31.184,52.786 30.748,53.222 C2.2@30.748,54.623 ; RMREG.2@55.442,52.854 55.575,52.72 57.338,52.72 Q1.3@57.493,52.566
  Top Layer w0.5: v1(56.304,53.84) 56.309,53.836 Q1.2@57.493,53.836 ; Q1.3@57.493,52.566 Q1.2@57.493,53.836 ; Q1.1@57.493,55.106 Q1.2@57.493,53.836
  Bottom Layer w0.3: v1(5.96,25.115) 5.919,25.156 5.919,28.692 15.163,37.935 15.163,54.373 16.281,55.491 VREG.1@24.144,55.491 ; v1(30.087,54.429) 30.401,54.742 55.456,54.742 56.304,53.894 v1(56.304,53.84)
VTREF: C11.2 C14.2 C52.2 C53.2 C54.2 C55.2 C56.2 JP1.3 R34.2 R45.2 R46.2 R47.2 R48.2 R49.2 U1.19 VTREF.1 | length 96
  Top Layer w0.2: VTREF.1@24.144,53.461 24.304,53.301 29.639,53.301 v1(30.207,52.733)
  Top Layer w0.3: v1(5.673,24.296) 5.639,24.262 5.639,18.747 JP1.3@6.348,18.038 ; v1(30.207,52.733) 30.255,52.685 30.37,52.685 30.769,52.286 U1.19@32.116,52.286 ; R34.2@46.844,59.075 46.851,59.068 v1(46.851,58.094)
  Bottom Layer w0.3: v1(5.673,24.296) 5.639,24.296 5.639,24.329 5.281,24.687 5.281,31.228 7.8,33.747 7.8,34.706 R49.2@7.657,34.849 7.8,34.992 C56.2@7.8,36.628 7.8,38.262 R48.2@7.657,38.405 7.8,38.548 7.8,41.818 R47.2@7.657,41.961 7.784,42.088 7.784,45.39 R46.2@7.657,45.517 7.784,45.644 7.784,48.946 R45.2@7.657,49.073 7.784,49.2 C52.2@7.784,50.851 7.784,56.12 8.449,56.785 28.734,56.785 29.155,56.363 C14.2@29.155,55.524 29.255,55.424 C14.2@29.255,55.224 ; C14.2@29.212,55.224 29.212,53.299 29.262,53.249 29.344,53.249 29.821,52.772 30.168,52.772 v1(30.207,52.733) ; C14.2@29.255,55.295 29.305,55.245 46.48,55.245 46.851,55.617 v1(46.851,58.094)
pads on no net: M1.1 M2.1 M3.1 M4.1

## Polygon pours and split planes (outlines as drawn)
GND on Top Layer "Top Layer-GND" (solid, remove dead copper, pour order 108): 56.21,63.523 ccw(c56.759,63.523) 56.759,62.974 75.545,62.974 75.545,93.016 ccw(c72.705,91.905) 73.747,94.771 20.398,94.771 20.398,89.459 30.848,89.459 cw(c30.848,88.764) 31.543,88.764 31.543,85.252 ccw(c32.245,85.252) 32.245,84.55 41.377,84.55 cw(c41.377,83.846) 42.081,83.846 42.081,78.226 ccw(c42.793,78.226) 42.793,77.514 55.535,77.514 cw(c55.535,76.839) 56.21,76.839
GND_BMS on Top Layer "Top Layer-GND_BMS" (solid, remove dead copper, pour order 99): 75.697,61.123 ccw(c75.697,61.275) 75.755,61.135 75.755,20.071 7.048,20.071 cw(c7.048,20.656) 6.463,20.656 6.463,25.357 ccw(c6.133,25.357) 6.133,25.686 4.665,25.686 ccw(c4.665,25.376) 4.354,25.376 4.354,11.823 ccw(c4.893,11.823) 4.893,11.284 10.955,11.284 10.955,-0.147 3.085,-0.147 cw(c3.084,2.983) -0.045,2.983 -0.045,20.071 -0.046,20.071 -0.046,70.915 8.516,70.915 ccw(c8.516,71.629) 9.231,71.63 9.231,72.346 cw(c10.955,72.346) 10.955,74.07 cw(c10.955,72.342) 12.683,72.342 12.683,71.629 ccw(c13.4,71.629) 13.4,70.912 20.34,70.912 ccw(c20.34,71.402) 20.83,71.402 20.83,86.422 ccw(c20.336,86.422) 20.335,86.916 13.39,86.916 ccw(c13.39,86.211) 12.685,86.211 12.685,85.5 cw(c10.946,85.5) 10.946,83.762 cw(c10.946,85.48) 9.227,85.481 9.227,86.194 ccw(c8.512,86.194) 8.511,86.91 -0.046,86.91 -0.046,91.905 cw(c3.003,91.905) 2.564,94.923 2.611,94.955 18.546,94.955 18.546,88.343 ccw(c19.258,88.343) 19.258,87.631 28.99,87.631 cw(c28.99,86.931) 29.69,86.931 29.69,83.359 ccw(c30.376,83.359) 30.376,82.673 39.544,82.673 cw(c39.544,81.987) 40.23,81.987 40.23,76.293 ccw(c40.869,76.293) 40.869,75.654 53.696,75.654 cw(c53.696,74.992) 54.358,74.992 54.358,61.802 ccw(c55.036,61.802) 55.036,61.124 75.696,61.124
GND_EXT on Top Layer "Top Layer-GND_EXT" (solid, remove dead copper, pour order 93): 9.826,15.499 10.56,15.499 cw(c10.56,15.147) 10.912,15.147 10.912,12.941 ccw(c11.715,12.941) 11.715,12.138 15.41,12.138 cw(c15.41,11.533) 16.015,11.533 16.03,-0.092 72.712,-0.092 ccw(c72.713,2.958) 75.763,2.958 75.763,18.918 10.209,18.918 ccw(c10.209,18.535) 9.826,18.535
NetC3_2 on Top Layer "Top Layer-NetC3_2" (solid, pour order 90): 45.627,52.434 45.627,52.158 45.649,52.136 46.937,52.136 46.937,52.143 48.472,52.143 cw(c48.472,50.544) 49.539,51.735 52.631,48.965 ccw(c53.54,49.875) 53.048,48.687 54.014,48.287 54.774,47.779 59.482,43.071 62.629,39.924 ccw(c62.901,40.196) 62.901,39.811 64.886,39.811 64.886,56.469 ccw(c63.904,56.469) 63.904,57.451 59.226,57.451 ccw(c59.226,56.881) 58.656,56.881 58.656,50.646 cw(c58.406,50.646) 58.405,50.396 54.508,50.401 cw(c54.511,52.517) 53.032,51.003 51.144,52.846 ccw(c49.988,51.662) 49.986,53.317 46.724,53.315 46.634,53.315 46.634,53.254 ccw(c48.227,51.034) 46.141,52.798 45.966,52.591 cw(c45.627,52.878)
GND on Bottom Layer "Top Layer-GND_BMS" (solid, remove dead copper, pour order 98): 20.398,89.459 30.848,89.459 cw(c30.848,88.764) 31.543,88.764 31.543,85.252 ccw(c32.245,85.252) 32.245,84.55 41.377,84.55 cw(c41.377,83.846) 42.081,83.846 42.081,78.226 ccw(c42.793,78.226) 42.793,77.514 55.535,77.514 cw(c55.535,76.839) 56.21,76.839 56.21,63.523 ccw(c56.759,63.523) 56.759,62.974 75.545,62.974 75.545,93.016 ccw(c72.705,91.905) 73.747,94.771 20.398,94.771
GND_BMS on Bottom Layer "Top Layer-GND_BMS" (solid, remove dead copper, pour order 97): 75.697,61.123 ccw(c75.697,61.275) 75.755,61.135 75.755,20.071 7.048,20.071 cw(c7.048,20.656) 6.463,20.656 6.463,25.357 ccw(c6.133,25.357) 6.133,25.686 4.665,25.686 ccw(c4.665,25.376) 4.354,25.376 4.354,11.823 ccw(c4.893,11.823) 4.893,11.284 10.955,11.284 10.955,-0.147 3.085,-0.147 cw(c3.084,2.983) -0.045,2.983 -0.045,20.071 -0.046,20.071 -0.046,70.915 8.516,70.915 ccw(c8.516,71.629) 9.231,71.63 9.231,72.346 cw(c10.955,72.346) 10.955,74.07 cw(c10.955,72.342) 12.683,72.342 12.683,71.629 ccw(c13.4,71.629) 13.4,70.912 20.34,70.912 ccw(c20.34,71.402) 20.83,71.402 20.83,86.422 ccw(c20.336,86.422) 20.335,86.916 13.39,86.916 ccw(c13.39,86.211) 12.685,86.211 12.685,85.5 cw(c10.946,85.5) 10.946,83.762 cw(c10.946,85.48) 9.227,85.481 9.227,86.194 ccw(c8.512,86.194) 8.511,86.91 -0.046,86.91 -0.046,91.905 cw(c3.003,91.905) 2.564,94.923 2.611,94.955 18.546,94.955 18.546,88.343 ccw(c19.258,88.343) 19.258,87.631 28.99,87.631 cw(c28.99,86.931) 29.69,86.931 29.69,83.359 ccw(c30.376,83.359) 30.376,82.673 39.544,82.673 cw(c39.544,81.987) 40.23,81.987 40.23,76.293 ccw(c40.869,76.293) 40.869,75.654 53.696,75.654 cw(c53.696,74.992) 54.358,74.992 54.358,61.802 ccw(c55.036,61.802) 55.036,61.124 75.696,61.124
GND_EXT on Bottom Layer "Bottom Layer-GND_EXT" (solid, remove dead copper, pour order 95): 9.826,15.499 10.56,15.499 cw(c10.56,15.147) 10.912,15.147 10.912,12.941 ccw(c11.715,12.941) 11.715,12.138 15.41,12.138 cw(c15.41,11.533) 16.015,11.533 16.03,-0.092 72.712,-0.092 ccw(c72.713,2.958) 75.763,2.958 75.763,18.918 10.209,18.918 ccw(c10.209,18.535) 9.826,18.535
NetC3_2 on Bottom Layer "Bottom Layer-NetC3_2" (solid, pour order 91): 62.901,39.811 64.886,39.811 64.886,56.449 ccw(c63.884,56.449) 63.884,57.451 59.094,57.451 ccw(c59.094,57.013) 58.656,57.013 58.656,50.646 cw(c58.65,50.646) 58.656,50.645 58.656,44.482 ccw(c60.07,44.482) 59.07,43.483 59.482,43.071 62.629,39.924 ccw(c62.901,40.196)
NetC3_2 on Bottom Layer "Bottom Layer-NetC3_2 1" (solid, pour order 92): 54.633,50.4 54.811,50.222 58.276,50.222 58.455,50.401 cw(c58.406,50.646) 58.405,50.396
GND on Layer 1 "Top Layer-GND_BMS" (solid, remove dead copper, pour order 103): 20.398,89.459 30.848,89.459 cw(c30.848,88.764) 31.543,88.764 31.543,85.252 ccw(c32.245,85.252) 32.245,84.55 41.377,84.55 cw(c41.377,83.846) 42.081,83.846 42.081,78.226 ccw(c42.793,78.226) 42.793,77.514 55.535,77.514 cw(c55.535,76.839) 56.21,76.839 56.21,63.523 ccw(c56.759,63.523) 56.759,62.974 75.545,62.974 75.545,93.016 ccw(c72.705,91.905) 73.747,94.771 20.398,94.771
GND_BMS on Layer 1 "Top Layer-GND_BMS" (solid, remove dead copper, pour order 101): 75.697,61.123 ccw(c75.697,61.275) 75.755,61.135 75.755,20.071 7.048,20.071 cw(c7.048,20.656) 6.463,20.656 6.463,25.357 ccw(c6.133,25.357) 6.133,25.686 4.665,25.686 ccw(c4.665,25.376) 4.354,25.376 4.354,11.823 ccw(c4.893,11.823) 4.893,11.284 10.955,11.284 10.955,-0.147 3.085,-0.147 cw(c3.084,2.983) -0.045,2.983 -0.045,20.071 -0.046,20.071 -0.046,70.915 8.516,70.915 ccw(c8.516,71.629) 9.231,71.63 9.231,72.346 cw(c10.955,72.346) 10.955,74.07 cw(c10.955,72.342) 12.683,72.342 12.683,71.629 ccw(c13.4,71.629) 13.4,70.912 20.34,70.912 ccw(c20.34,71.402) 20.83,71.402 20.83,86.422 ccw(c20.336,86.422) 20.335,86.916 13.39,86.916 ccw(c13.39,86.211) 12.685,86.211 12.685,85.5 cw(c10.946,85.5) 10.946,83.762 cw(c10.946,85.48) 9.227,85.481 9.227,86.194 ccw(c8.512,86.194) 8.511,86.91 -0.046,86.91 -0.046,91.905 cw(c3.003,91.905) 2.564,94.923 2.611,94.955 18.546,94.955 18.546,88.343 ccw(c19.258,88.343) 19.258,87.631 28.99,87.631 cw(c28.99,86.931) 29.69,86.931 29.69,83.359 ccw(c30.376,83.359) 30.376,82.673 39.544,82.673 cw(c39.544,81.987) 40.23,81.987 40.23,76.293 ccw(c40.869,76.293) 40.869,75.654 53.696,75.654 cw(c53.696,74.992) 54.358,74.992 54.358,61.802 ccw(c55.036,61.802) 55.036,61.124 75.696,61.124
GND_EXT on Layer 1 "Layer 1-GND_EXT" (solid, remove dead copper, pour order 94): 9.826,15.499 10.56,15.499 cw(c10.56,15.147) 10.912,15.147 10.912,12.941 ccw(c11.715,12.941) 11.715,12.138 15.41,12.138 cw(c15.41,11.533) 16.015,11.533 16.03,-0.092 72.712,-0.092 ccw(c72.713,2.958) 75.763,2.958 75.763,18.918 10.209,18.918 ccw(c10.209,18.535) 9.826,18.535
GND on Layer 2 "Top Layer-GND_BMS" (solid, remove dead copper, pour order 104): 20.398,89.459 30.848,89.459 cw(c30.848,88.764) 31.543,88.764 31.543,85.252 ccw(c32.245,85.252) 32.245,84.55 41.377,84.55 cw(c41.377,83.846) 42.081,83.846 42.081,78.226 ccw(c42.793,78.226) 42.793,77.514 55.535,77.514 cw(c55.535,76.839) 56.21,76.839 56.21,63.523 ccw(c56.759,63.523) 56.759,62.974 75.545,62.974 75.545,93.016 ccw(c72.705,91.905) 73.747,94.771 20.398,94.771
GND_BMS on Layer 2 "Top Layer-GND_BMS" (solid, remove dead copper, pour order 102): 75.697,61.123 ccw(c75.697,61.275) 75.755,61.135 75.755,20.071 7.048,20.071 cw(c7.048,20.656) 6.463,20.656 6.463,25.357 ccw(c6.133,25.357) 6.133,25.686 4.665,25.686 ccw(c4.665,25.376) 4.354,25.376 4.354,11.823 ccw(c4.893,11.823) 4.893,11.284 10.955,11.284 10.955,-0.147 3.085,-0.147 cw(c3.084,2.983) -0.045,2.983 -0.045,20.071 -0.046,20.071 -0.046,70.915 8.516,70.915 ccw(c8.516,71.629) 9.231,71.63 9.231,72.346 cw(c10.955,72.346) 10.955,74.07 cw(c10.955,72.342) 12.683,72.342 12.683,71.629 ccw(c13.4,71.629) 13.4,70.912 20.34,70.912 ccw(c20.34,71.402) 20.83,71.402 20.83,86.422 ccw(c20.336,86.422) 20.335,86.916 13.39,86.916 ccw(c13.39,86.211) 12.685,86.211 12.685,85.5 cw(c10.946,85.5) 10.946,83.762 cw(c10.946,85.48) 9.227,85.481 9.227,86.194 ccw(c8.512,86.194) 8.511,86.91 -0.046,86.91 -0.046,91.905 cw(c3.003,91.905) 2.564,94.923 2.611,94.955 18.546,94.955 18.546,88.343 ccw(c19.258,88.343) 19.258,87.631 28.99,87.631 cw(c28.99,86.931) 29.69,86.931 29.69,83.359 ccw(c30.376,83.359) 30.376,82.673 39.544,82.673 cw(c39.544,81.987) 40.23,81.987 40.23,76.293 ccw(c40.869,76.293) 40.869,75.654 53.696,75.654 cw(c53.696,74.992) 54.358,74.992 54.358,61.802 ccw(c55.036,61.802) 55.036,61.124 75.696,61.124
GND_EXT on Layer 2 "Layer 2-GND_EXT" (solid, remove dead copper, pour order 96): 9.826,15.499 10.56,15.499 cw(c10.56,15.147) 10.912,15.147 10.912,12.941 ccw(c11.715,12.941) 11.715,12.138 15.41,12.138 cw(c15.41,11.533) 16.015,11.533 16.03,-0.092 72.712,-0.092 ccw(c72.713,2.958) 75.763,2.958 75.763,18.918 10.209,18.918 ccw(c10.209,18.535) 9.826,18.535

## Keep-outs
Keep-Out Layer:
  lines w0.1: 0.025,91.97 cw(c3.013,91.97) 3.013,94.958 72.71,94.958 cw(c72.71,91.894) 75.774,91.894 75.749,2.933 cw(c72.749,2.933) 72.749,-0.067 3.143,-0.067 cw(c3.096,2.98) 0.049,2.933 0.025,91.97

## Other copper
Bottom Layer:
  rectangle net ISENSEM: 29.698,11.092 31.611,13.652
  rectangle net ISENSEP: 25.897,11.092 27.81,13.652
  rectangle net NetFB4_2: 55.158,21.829 62.392,23.029
  rectangle net NetFB6_2: 46.691,21.829 53.924,23.029
  rectangle net NetFB8_2: 38.223,21.829 45.457,23.029
  rectangle net NetFB10_2: 29.755,21.829 36.989,23.029
  rectangle net NetFB12_2: 21.288,21.829 28.521,23.029
  rectangle net NetFB14_2: 12.82,21.829 20.054,23.029

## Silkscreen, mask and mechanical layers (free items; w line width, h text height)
Top Overlay:
  drawing of 1821 lines, arcs and shapes, not listed
  text "USB compatible only with the BMS system" at 20.957,86.196 h1.5 r270
  text "GND" at 67.655,84.824 h1.2 r270
  text "VDD" at 67.607,82.409 h1.3 r270
  text "VIO" at 67.61,79.708 h1.3 r270
  text "GND" at 67.656,77.213 h1.2 r270
  text "STEVAL$BMS114TXA" at 25.822,36.913 h2.5
Bottom Overlay:
  drawing of 1484 lines, arcs and shapes, not listed
Bottom Solder:
  rectangle: 29.698,11.092 31.611,13.652
  rectangle: 25.897,11.092 27.81,13.652
  rectangle: 33.217,45.011 42.217,54.011
Dimensions:
  lines w0.1: 3.012,94.958 ccw(c3.012,91.958) 0.012,91.958 0.012,2.958 ccw(c3.06,3.005) 3.106,-0.042 72.713,-0.042 ccw(c72.713,2.958) 75.713,2.958 75.689,92.059 ccw(c72.814,92.059) 72.814,94.933 3.014,94.958

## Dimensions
75.689,92.059 to 0.012,91.958 on Dimensions
72.814,94.933 to 72.713,-0.042 on Dimensions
